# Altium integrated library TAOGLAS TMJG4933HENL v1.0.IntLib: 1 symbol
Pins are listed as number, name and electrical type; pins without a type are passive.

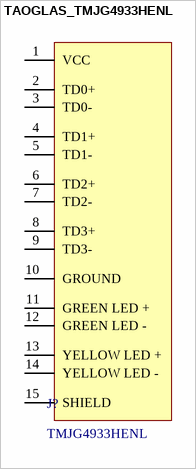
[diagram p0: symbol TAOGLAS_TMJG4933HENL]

## TAOGLAS_TMJG4933HENL
designator J?, comment TMJG4933HENL
RJ45 connector with integrated magnetics 1G Base-T Single Port Tab-DOWN with right angle THT mount and LEDs; ComponentLibStatus: Created; MFG: Taoglas; Temp_High: +85C; Temp_Low: -40C
footprint TAOGLAS_TMJG4933HENL (RJ45 connector with integrated magnetics 1G Base-T Single Port Tab-DOWN with right angle THT mount and LEDs)
pins: 1 VCC, 2 TD0+, 3 TD0-, 4 TD1+, 5 TD1-, 6 TD2+, 7 TD2-, 8 TD3+, 9 TD3-, 10 GROUND, 11 GREEN LED +, 12 GREEN LED -, 13 YELLOW LED +, 14 YELLOW LED -, 15 SHIELD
